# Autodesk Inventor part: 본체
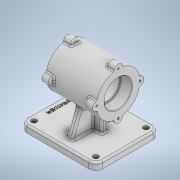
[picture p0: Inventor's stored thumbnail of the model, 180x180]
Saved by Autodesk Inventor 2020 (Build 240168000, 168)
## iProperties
Created: 2022-11
Part Number: 본체
Material: 일반
Document SubType Name: Modeling
Designer: owner
Density: 1 g/cm^3
Appearance: 기본값
Mass: 450.145 g
Surface Area: 796.917 cm^2
Volume: 450.145 cm^3
Author: owner
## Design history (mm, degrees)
sketch "스케치7"
  geometry: L1 (65, 55)-(-65, 55); L2 (-65, 55)-(-65, -55); L3 (-65, -55)-(65, -55); L4 (65, -55)-(65, 55); L5 (65, 55)-(-65, -55); L6 (-65, 55)-(65, -55); 1 further point
  constraints: 12 end point, 2 midpoint, 2 parallel, 1 horizontal, 1 perpendicular
  dimensions: "d28" = 130 distance of L3.end L2.end; "d29" = 110 distance of L2.end L1.end
extrude "돌출6" new body sketch "스케치7" distance "d30" = 12; taper "d31" = 0 deg
node "작업 평면3"
sketch "스케치8"
  geometry: L1 (0, 0)-(110, 0) reference; C1 r 37 at (55, 82); 2 further points
  constraints: 1 centre point, 1 midpoint, 1 vertical alignment
  dimensions: "d33" = 74 diameter of C1; "d34" = 82 distance from line of L1 C1.centre
extrude "돌출7" join sketch "스케치8" stored distance "d35" = 87; taper "d36" = 0 deg
sketch "스케치9"
  geometry: C1 r 37 at (0, 0) reference; 2 further points
  constraints: 1 coincident
hole "구멍2" sketch "스케치9" at (0, 0) diameter "d37" = 42; stored, may be unused: countersink angle "d41" = 90 deg, drill point angle "d43" = 118 deg; dims "d38" = 8, "d39" = 4, "d40" = 2, "d42" = 10
sketch "스케치10"
  geometry: L1 (-55, -82)-(55, -82) reference; C1 r 23.5 at (0, 0); 2 further points
  constraints: 1 centre point, 1 midpoint, 1 vertical alignment
  dimensions: "d44" = 47 diameter of C1
extrude "돌출8" cut sketch "스케치10" distance "d45" = 19; taper "d46" = 0 deg
sketch "스케치11"
  geometry: C1 r 23.5 at (0, 0); 1 further point
  constraints: 1 centre point
  dimensions: "d47" = 47 diameter of C1
extrude "돌출9" cut sketch "스케치11" distance "d48" = 19; taper "d49" = 0 deg
sketch "스케치12"
  geometry: A1 r 37 centre (0, 0) between (0, 37) and (-6.969, 36.338) reference; A2 r 7 centre (0, 37) between (6.969, 36.338) and (-6.969, 36.338); 1 further point
  constraints: 5 point on circle, 1 centre point, 1 vertical alignment
  dimensions: "d50" = 14 diameter of A2
extrude "돌출10" join sketch "스케치12" distance "d51" = 14; taper "d52" = 0 deg
sketch "스케치13"
  geometry: C1 r 23.5 at (55, 82) reference; A1 r 37 centre (55, 82) between (48.031, 118.338) and (61.969, 118.338) reference; A2 r 7 centre (55, 119) between (61.969, 118.338) and (48.031, 118.338) reference; 1 further point
hole "구멍3" sketch "스케치13" at (55, 119) diameter "d53" = 3.242; stored, may be unused: countersink angle "d57" = 90 deg, drill point angle "d59" = 118 deg; dims "d54" = 8, "d55" = 4, "d56" = 2, "d58" = 10
fillet "모깎기3" dims "d60" = 3
fillet "모깎기4" dims "d61" = 3
sketch "스케치17"
  geometry: L1 (110, 12)-(0, 12) reference; L2 (14, 12)-(29.664, 55.036); L3 (96, 12)-(80.171, 55.489); L4 (110, 0)-(110, 12) reference; L5 (0, 0)-(0, 12) reference; C1 r 21 at (55, 82) reference; C2 r 21 at (55, 82) reference; A1 r 37 centre (55, 82) between (45.896, 117.863) and (64.104, 117.863) reference; 5 further points
  constraints: 4 end point, 2 point on line, 1 coincident, 1 point on circle
  dimensions: "d69" = 14 distance from line of L4 L3.start; "d70" = 110 deg angle of L1 L3; "d71" = 14 distance from line of L5 point (14, 12); "d72" = 110 deg angle of L1 L2
extrude "돌출11" join sketch "스케치17" stored distance "d73" = 10; taper "d74" = 0 deg
sketch "스케치18"
  geometry: L1 (65, 12)-(-65, 12) reference; L2 (-15, 12)-(-15, 36.909); L3 (25, 12)-(25, 36.909); L4 (5, -25.2)-(5, 151.2) reference; 1 further point
  constraints: 4 end point, 2 point on line, 1 perpendicular, 1 vertical
  dimensions: "d78" = 20 distance between parallel lines of L4 L2; "d79" = 20 distance between parallel lines of L4 L3
feature "리브1" sketch "스케치18" dims "d80" = 1, "d81" = 10, "d82" = 0, "d83" = 0, "d84" = 1, "d85" = 1
fillet "모깎기5" dims "d86" = 12
sketch "스케치19"
  geometry: C1 r 4.5 at (-53, -43); A1 r 12 centre (-53, -43) between (-65, -43) and (-53, -55) reference; 1 further point
  constraints: 1 centre point, 1 coincident
  dimensions: "d87" = 9 diameter of C1
extrude "돌출12" cut sketch "스케치19" distance "d88" = 12; taper "d89" = 0 deg
fillet "모깎기6" dims "d90" = 3
fillet "모깎기7" dims "d91" = 3
fillet "모깎기8" dims "d92" = 3
fillet "모깎기9" dims "d93" = 1
chamfer "모따기1" distance "d94" = 1; stored, may be unused: second distance "d95" = 2, angle "d96" = 45 deg
sketch "스케치20"
  geometry: C1 r 4.5 at (-53, -43) reference; 2 further points
  constraints: 1 vertical alignment, 1 other
feature "엠보싱1" dims "d28" = 130, "d29" = 110, "d97" = 0.5, "d98" = 0
node "솔리드2"
pattern_circular "원형 패턴3" dims "d76" = 360 deg
mirror "미러3"
mirror "미러4"
mirror "미러7"
mirror "미러8"
node "투영된 루프1"
node "투영된 루프2"
feature "A9D066F2-1C7D-4E18-AEED-F7BC21143FA4" dims "d37" = 42, "d38" = 8, "d39" = 4, "d40" = 2, "d41" = 90 deg, "d42" = 10, "d43" = 118 deg
